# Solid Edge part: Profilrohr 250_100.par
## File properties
Username: ahadarics
Dokumentum tartalom típus: 0
Author: ahadarics
Last saved by: ahadarics
Revision: 81
Sűrűség: 0,000 kg/m^3
Pontosság: 0,990
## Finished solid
Body 1: solid body, 8 faces, 12 edges, 6 vertices.
  Faces by surface: cone 4, cylinder 2, plane 2
  Edges by curve: circle 8, line 4
Bounding box of the edges (mm): 262.000 x 180.000 x 262.000, from (-131, -127.5, -131) to (131, 52.5, 131).
Cylindrical faces by radius (mm): R125 x1, R131 x1
Conical faces (half-angle, radius in mm at the cone's reference point): 45 deg R125.25 x2, 45 deg R130.9 x2
Planar faces by outward normal: +y 1, -y 1
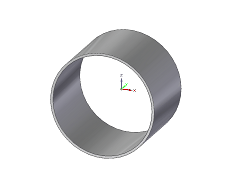
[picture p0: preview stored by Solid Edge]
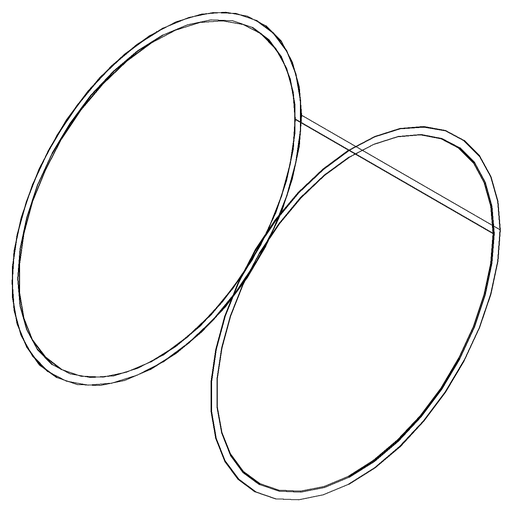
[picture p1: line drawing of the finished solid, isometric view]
